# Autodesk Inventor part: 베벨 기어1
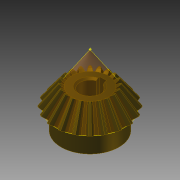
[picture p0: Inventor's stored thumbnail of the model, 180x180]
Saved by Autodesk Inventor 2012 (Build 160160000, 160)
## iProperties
Created: 2012-07
Part Number: 베벨 기어1
Material: Steel, Mild
Document SubType Name: Modeling
Designer: SeoGD™ [www.esajin.kr]
Categories: <?xml version="1.0" encoding="UTF-16"?> <MemberInstance><Categories><FamilyTemplate><FamilyTemplateParameter ValueType="xs:double" Id="1" ObjectReferenceKey="da
Mass: 60.9118 g
Surface Area: 34.3074 cm^2
Volume: 7.7496 cm^3
Density: 7.86 g/cm^3
CustomPartVersion: 1
Author: SeoGD™ [www.esajin.kr]
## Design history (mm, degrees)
node "맨 위 점"
node "메쉬 평면2"
sketch "톱니 본체 스케치"
  geometry: L1 (0, 0)-(18.003, -31.331); L2 (18.003, -31.331)-(21.664, -28.891); L3 (21.664, -28.891)-(0, 0); L4 (20, -30)-(0, 0); L5 (10.813, -18.818)-(13.012, -17.352); L6 (18.003, -31.331)-(10.813, -18.818); L7 (21.664, -28.891)-(13.012, -17.352); L8 (0, -39.387)-(0, 6.564) reference; L9 (0, -30)-(21.664, -30)
  constraints: 16 end point, 4 point on line, 3 perpendicular, 2 collinear, 1 horizontal alignment, 1 vertical alignment
  dimensions: "d0" = 40 diameter of L4.start L8 (= da_de); "d1" = 36.00616 diameter of L1.end L8 (= da_dfe); "d2" = 43.3282 diameter of L2.end L8 (= da_dae); "d3" = 14.4 distance between parallel lines of L2 L5 (= da_b); "d4" = 28.8906 vertical distance of L2.end L1.start (= da_ve)
revolve "톱니 본체" sketch "톱니 본체 스케치" stored, may be unused: angle "d5" = 90 deg
node "시작점"
node "톱니 평면"
sketch "시작 스케치"
  geometry: L1 (0, -23.505)-(0, 10.645) reference; L2 (-0.834, -2.928)-(0.834, -2.928); A1 r 8.898 centre (-9.698, -3.713) between (-0.834, -2.928) and (-3.903, 3.04); A2 r 8.898 centre (9.698, -3.713) between (3.903, 3.04) and (0.834, -2.928); A3 r 27.357 centre (0, -24.037) between (3.903, 3.04) and (-3.903, 3.04); 1 further point
  constraints: 6 point on circle, 3 centre point, 3 symmetric about line, 2 end point, 1 coincident, 1 perpendicular, 1 other
  dimensions: "d7" = 8.89846 radius of A1 (= fd_rr); "d8" = 9.69794 horizontal distance of point (0, -24.037) A1.centre (= fd_x); "d9" = 20.32439 vertical distance of point (0, -24.037) A1.centre (= fd_y); "d57" = 27.35701 radius of A3 (= 0.5 x fd_dva + 0.3 x da_he); "d58" = 21.10901 distance from line of A3.centre L2 (= 0.5 x fd_dva - 1.12 x da_he)
node "끝점"
  node "끝 평면"
sketch "3D 스케치 오른쪽"
  node "Helical Curve Right" dims "d65" = 229.90621 (computed from da_dm, da_delta, da_beta), "d66" = 31.5, "d67" = 40 (= da_de), "d68" = -5.88003 (= -da_delta), "d69" = 12.16458 (computed from fd_loft, da_delta)
node "끝 평면 오른쪽"
sketch "끝 스케치 오른쪽"
  geometry: L1 (0, -22.649)-(0, 12.15) reference; L2 (-0.497, -1.72)-(0.497, -1.72); A1 r 5.299 centre (-5.775, -2.187) between (-0.497, -1.72) and (-2.324, 1.834); A2 r 5.299 centre (5.775, -2.187) between (2.324, 1.834) and (0.497, -1.72); A3 r 16.291 centre (0, -14.29) between (2.324, 1.834) and (-2.324, 1.834); 1 further point
  constraints: 6 point on circle, 3 centre point, 3 symmetric about line, 2 end point, 1 coincident, 1 perpendicular, 1 other
  dimensions: "d70" = 5.77526 horizontal distance of A3.centre A1.centre (computed from fd_x, fd_ratio); "d71" = 12.10346 vertical distance of point (0, -14.29) A1.centre (computed from fd_y, fd_ratio); "d72" = 5.29916 radius of A1 (computed from fd_rr, fd_ratio); "d73" = 12.57071 distance from line of point (0, -14.29) L2 (computed from d58, fd_ratio); "d74" = 16.29149 radius of A3 (computed from d57, fd_ratio)
feature "로프트 오른쪽" sketch "끝 스케치 오른쪽" dims "d75" = 0, "d77" = 0, "d79" = 0, "d80" = 90 deg, "d85" = 20, "d92" = 90 deg, "d93" = 90 deg, "da_teethtype" = 0 [user parameter]
sketch "3D 스케치 왼쪽"
  node "Helical Curve Left" dims "d26" = 229.90621 (computed from da_dm, da_delta, da_beta), "d27" = 12.16458 (computed from fd_loft, da_delta), "d28" = 40 (= da_de), "d29" = -5.88003 (= -da_delta)
node "끝 평면 왼쪽"
sketch "끝 스케치 왼쪽" dims "d56" = 10.82768 (derived)
  geometry: L1 (0, -35.087)-(0, 18.089) reference; L2 (-0.497, -1.716)-(0.497, -1.716); A1 r 5.299 centre (-5.775, -2.183) between (-0.497, -1.716) and (-2.324, 1.838); A2 r 5.299 centre (5.775, -2.183) between (2.324, 1.838) and (0.497, -1.716); A3 r 16.291 centre (0, -14.287) between (2.324, 1.838) and (-2.324, 1.838); 2 further points; 1 other entity
  constraints: 6 point on circle, 3 centre point, 3 symmetric about line, 2 end point, 1 coincident, 2 other
  dimensions: "d30" = 5.29916 radius of A1 (computed from fd_rr, fd_ratio); "d31" = 5.77526 horizontal distance of point (0, -14.287) A1.centre (computed from fd_x, fd_ratio); "d32" = 12.10346 vertical distance of A1.centre point (0, -14.287) (computed from fd_y, fd_ratio); "d61" = 16.29149 radius of A3 (computed from d57, fd_ratio); "d62" = 12.57071 distance from line of point (0, -14.287) L2 (computed from d58, fd_ratio)
feature "로프트 왼쪽" sketch "끝 스케치 왼쪽" dims "d35" = 0, "d37" = 0, "d39" = 0, "d40" = 90 deg, "d84" = 10, "d90" = 90 deg, "d91" = 90 deg, "da_teethtype" = 0 [user parameter]
sketch "본체 스케치"
  geometry: L1 (0, -35.038)-(0, -19.531) reference; L2 (18.003, -31.331)-(10.813, -18.818) reference; L3 (10.813, -18.818)-(0, -18.818); L4 (18.003, -31.331)-(0, -31.331)
  constraints: 4 end point, 2 perpendicular, 2 point on line
revolve "본체 고정" sketch "본체 스케치" stored, may be unused: angle "d46" = 90 deg
sketch "Sketch6"
  geometry: L1 (20, -30)-(0, 0) reference; L2 (0, -37.8)-(0, 6.3) reference
feature "피치 지름" sketch "Sketch6" dims angle "d47" = 90 deg
sketch "스케치8"
  geometry: C1 r 17 at (0, 0); 1 further point
  constraints: 1 centre point, 1 coincident
  dimensions: "d94" = 34 diameter of C1
extrude "돌출1" join sketch "스케치8" distance "d95" = 10; taper "d96" = 0 deg
sketch "스케치9"
  geometry: 1 further point
hole "구멍1" sketch "스케치9" at (0, 0) diameter "d97" = 12; stored, may be unused: countersink angle "d101" = 90 deg, drill point angle "d103" = 118 deg; dims "d98" = 6, "d99" = 4, "d100" = 2, "d102" = 8
sketch "스케치10"
  geometry: 1 further point
sketch "스케치11"
  geometry: 1 further point
sketch "스케치12"
  geometry: L1 (-2, 5.657)-(-2, 7.8); L2 (-2, 7.8)-(2, 7.8); L3 (2, 7.8)-(2, 5.657); A1 r 6 centre (0, 0) between (-2, 5.657) and (2, 5.657) reference; 1 further point
  constraints: 6 end point, 2 parallel, 2 point on circle, 1 perpendicular, 1 vertical
  dimensions: "d104" = 4 distance of L1.end L2.end; "d105" = 13.8 dimension on A1 L2
extrude "돌출2" cut sketch "스케치12" stored distance "d106" = 7; taper "d107" = 0 deg
chamfer "모따기1" distance "d108" = 1; stored, may be unused: second distance "d109" = 2, angle "d110" = 45 deg
body "Solid1"
feature "로프트" dims "d17" = 0, "d18" = 90 deg, "d19" = 0, "d20" = 90 deg, "d89" = 0, "da_teethtype" = 0 [user parameter]
pattern_circular "원형 패턴" dims angle "d22" = 360 deg, "d88" = 0, "da_teethtype" = 0 [user parameter]
pattern_circular "원형 패턴 오른쪽" dims angle "d82" = 360 deg, "da_teethtype" = 0 [user parameter]
pattern_circular "원형 패턴 왼쪽" dims angle "d42" = 360 deg, "da_teethtype" = 0 [user parameter]
sketch "끝 스케치"
  geometry: L1 (0, -15.359)-(0, 6.983) reference; L2 (-0.497, -1.72)-(0.497, -1.72); A1 r 5.299 centre (-5.775, -2.187) between (-0.497, -1.72) and (-2.324, 1.834); A2 r 5.299 centre (5.775, -2.187) between (2.324, 1.834) and (0.497, -1.72); A3 r 16.291 centre (0, -14.29) between (2.324, 1.834) and (-2.324, 1.834); 1 further point
  constraints: 6 point on circle, 3 centre point, 3 symmetric about line, 2 end point, 1 coincident, 1 other
  dimensions: "d12" = 5.29916 radius of A1 (computed from fd_rr, fd_ratio); "d15" = 5.77526 horizontal distance of A1.centre point (0, -14.29) (computed from fd_x, fd_ratio); "d16" = 12.10346 vertical distance of A1.centre point (0, -14.29) (computed from fd_y, fd_ratio); "d59" = 16.29149 radius of A3 (computed from d57, fd_ratio); "d60" = 12.57071 distance from line of A3.centre L2 (computed from d58, fd_ratio)
body "Srf1"
other parameters: "da_b" = 14.4 [user parameter; used in 2 equation terms], "da_de" = 40 [user parameter; used in 4 equation terms], "da_dae" = 43.3282 [user parameter; used in 2 equation terms], "da_dfe" = 36.00616 [user parameter; used in 1 equation term], "da_le" = 36.05551 [user parameter; used in 1 equation term], "da_omega" = 90 deg [user parameter; used in 1 equation term], "da_beta" = 0 [user parameter; used in 2 equation terms], "da_delta" = 5.88003 [user parameter; used in 8 equation terms], "da_alpha" = 20 deg [user parameter; used in 2 equation terms], "da_he" = 4.4 [user parameter; used in 4 equation terms], "da_ve" = 28.8906 [user parameter; used in 1 equation term], "fd_dv" = 48.07402 (computed from da_de, da_delta) [user parameter; used in 1 equation term], "fd_dva" = 52.07402 (computed from da_dae, da_delta) [user parameter; used in 3 equation terms], "fd_dvb" = 45.1748 (computed from fd_dv, da_alpha) [user parameter; used in 2 equation terms], "da_zv" = 240.37008 [user parameter; used in 1 equation term], "fd_loft" = 14.62 (= da_b + 0.05 x da_he) [user parameter; used in 4 equation terms], "fd_ratio" = 5.95514 (computed from da_le, fd_loft) [user parameter; used in 15 equation terms], "fd_rr" = 8.89846 (computed from fd_dd, fd_dvb) [user parameter; used in 6 equation terms], "fd_angle" = 0.66075 (computed from da_zv) [user parameter; used in 4 equation terms], "fd_x1" = 1.58709 (computed from da_dvw, fd_angle) [user parameter; used in 1 equation term], "fd_y1" = 23.98456 (computed from da_dvw, fd_angle) [user parameter; used in 1 equation term], "fd_x2" = 8.11084 (computed from fd_rr, fd_angle2, fd_angle) [user parameter; used in 1 equation term], "fd_y2" = 3.66016 (computed from fd_rr, fd_angle2, fd_angle) [user parameter; used in 1 equation term], "fd_x" = 9.69794 (= fd_x1 + fd_x2) [user parameter; used in 4 equation terms], "fd_y" = 20.32439 (= fd_y1 - fd_y2) [user parameter; used in 4 equation terms], "fd_angle2" = 3.57832 (computed from fd_dvb, fd_dd, da_alpha) [user parameter; used in 2 equation terms], "fd_dd" = 48.55402 (= fd_dva - 0.8 x da_he) [user parameter; used in 2 equation terms], "da_dvw" = 48.07402 [user parameter; used in 2 equation terms], "d11" = 14.62 (= fd_loft), "da_dm" = 32.01232 [user parameter; used in 2 equation terms], "da_x" = 0 [user parameter], "da_m" = 2 [user parameter], "d48" = 0, "d49" = 0, "d50" = 90 deg (= da_omega), "d51" = 9 deg (computed from da_z), "d52" = 0, "d53" = 0, "d54" = 0
